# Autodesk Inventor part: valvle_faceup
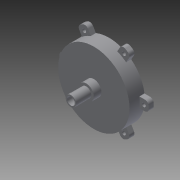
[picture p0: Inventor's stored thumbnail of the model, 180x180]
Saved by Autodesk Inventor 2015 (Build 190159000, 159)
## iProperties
Created: 2017-05
Part Number: valvle_faceup
Material: Generic
Document SubType Name: Modeling
Designer: mcalderon
Density: 1 g/cm^3
Appearance: Default
Author: mcalderon
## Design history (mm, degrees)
sketch "Sketch1"
  geometry: L1 (-25, 25)-(25, 25); L2 (25, 25)-(25, -25); L3 (25, -25)-(-25, -25); L4 (-25, -25)-(-25, 25); L5 (-25, 25)-(25, -25); L6 (25, 25)-(-25, -25); C1 r 25 at (0, 0); C2 r 28 at (0, 0); 1 further point
  constraints: 12 end point, 4 midpoint, 2 centre point, 2 parallel, 1 coincident, 1 horizontal, 1 perpendicular
  dimensions: "d0" = 50 diameter of C1; "d1" = 50 distance of L2.end L3.end; "d2" = 50 distance of L1.end L2.end; "d3" = 56 diameter of C2
extrude "Extrusion1" new body sketch "Sketch1" distance "d4" = 8; taper "d5" = 0 deg
sketch "Sketch2"
  geometry: L1 (-25, 0)-(-35, 0); L2 (-35, 0)-(-35, 1); L3 (-32, 4)-(-25, 4); L4 (-25, 4)-(-25, 0); L5 (-35, 0)-(-35, -1); L6 (-32, -4)-(-25, -4); L7 (-29.247, -4)-(-29.247, 4); L8 (-25, -4)-(-25, 0); L9 (-11.159, -27.329)-(-18.088, -23.329); L10 (-12.536, -29.713)-(-9.036, -23.651); L11 (-9.036, -23.651)-(-12.5, -21.651); L12 (-15.964, -19.651)-(-12.5, -21.651); L13 (-19.464, -25.713)-(-15.964, -19.651); L14 (-17.5, -30.311)-(-18.366, -29.811); L15 (-17.5, -30.311)-(-16.634, -30.811); L16 (18.088, -23.329)-(11.159, -27.329); L17 (19.464, -25.713)-(15.964, -19.651); L18 (15.964, -19.651)-(12.5, -21.651); L19 (9.036, -23.651)-(12.5, -21.651); L20 (12.536, -29.713)-(9.036, -23.651); L21 (17.5, -30.311)-(16.634, -30.811); L22 (17.5, -30.311)-(18.366, -29.811); L23 (29.247, 4)-(29.247, -4); L24 (32, 4)-(25, 4); L25 (25, 4)-(25, 0); L26 (25, -4)-(25, 0); L27 (32, -4)-(25, -4); L28 (35, 0)-(35, -1); L29 (35, 0)-(35, 1); L30 (11.159, 27.329)-(18.088, 23.329); L31 (12.536, 29.713)-(9.036, 23.651); L32 (9.036, 23.651)-(12.5, 21.651); L33 (15.964, 19.651)-(12.5, 21.651); L34 (19.464, 25.713)-(15.964, 19.651); L35 (17.5, 30.311)-(18.366, 29.811); L36 (17.5, 30.311)-(16.634, 30.811); L37 (-18.088, 23.329)-(-11.159, 27.329); L38 (-19.464, 25.713)-(-15.964, 19.651); L39 (-15.964, 19.651)-(-12.5, 21.651); L40 (-9.036, 23.651)-(-12.5, 21.651); L41 (-12.536, 29.713)-(-9.036, 23.651); L42 (-17.5, 30.311)-(-16.634, 30.811); L43 (-17.5, 30.311)-(-18.366, 29.811); C1 r 1.5 at (-31.163, 0); C2 r 1.5 at (-15.582, -26.988); C3 r 1.5 at (15.582, -26.988); C4 r 1.5 at (31.163, 0); C5 r 1.5 at (15.582, 26.988); C6 r 1.5 at (-15.582, 26.988); A1 r 3 centre (-32, -1) between (-35, -1) and (-32, -4); A2 r 3 centre (-32, 1) between (-32, 4) and (-35, 1); A3 r 3 centre (-16.866, -27.213) between (-19.464, -25.713) and (-18.366, -29.811); A4 r 3 centre (-15.134, -28.213) between (-16.634, -30.811) and (-12.536, -29.713); A5 r 3 centre (15.134, -28.213) between (12.536, -29.713) and (16.634, -30.811); A6 r 3 centre (16.866, -27.213) between (18.366, -29.811) and (19.464, -25.713); A7 r 3 centre (32, -1) between (32, -4) and (35, -1); A8 r 3 centre (32, 1) between (35, 1) and (32, 4); A9 r 3 centre (16.866, 27.213) between (19.464, 25.713) and (18.366, 29.811); A10 r 3 centre (15.134, 28.213) between (16.634, 30.811) and (12.536, 29.713); A11 r 3 centre (-15.134, 28.213) between (-12.536, 29.713) and (-16.634, 30.811); A12 r 3 centre (-16.866, 27.213) between (-18.366, 29.811) and (-19.464, 25.713); 14 further points
  constraints: 86 end point, 37 point on line, 24 point on circle, 18 centre point, 4 tangent, 3 vertical, 2 parallel, 2 symmetric about line, 1 equal radius, 1 horizontal, 1 horizontal alignment, 1 perpendicular, 152 other
  dimensions: "d6" = 10 distance of point (-35, 4) L3.end; "d7" = 4 distance of L1.end point (-35, 4); "d9" = 3 radius of A1; "d10" = 3 diameter of C1; "d13" = 360 deg dimension on point (0, 0) L7.start (derived)
extrude "Extrusion2" join sketch "Sketch2" distance "d15" = 4; taper "d16" = 0 deg
sketch "Sketch3"
  geometry: C1 r 28 at (0, 0); 1 further point
  constraints: 1 centre point, 1 coincident
  dimensions: "d17" = 56 diameter of C1
extrude "Extrusion3" join sketch "Sketch3" distance "d18" = 4; taper "d19" = 0 deg
sketch "Sketch4"
  geometry: C1 r 3.065 at (0, 0); 1 further point
  constraints: 1 centre point, 1 coincident
  dimensions: "d20" = 6.13 diameter of C1
extrude "Extrusion4" cut sketch "Sketch4" distance "d22" = 4; taper "d23" = 0 deg
sketch "Sketch5"
  geometry: C1 r 3.065 at (0, 0); C2 r 6 at (0, 0); 1 further point
  constraints: 2 centre point, 2 coincident
  dimensions: "d24" = 6.13 diameter of C1; "d25" = 12 diameter of C2
extrude "Extrusion5" join sketch "Sketch5" distance "d26" = 6; taper "d27" = 0 deg
sketch "Sketch6"
  geometry: C1 r 3.065 at (0, 0); C2 r 4 at (0, 0); 1 further point
  constraints: 2 centre point, 2 coincident
  dimensions: "d28" = 6.13 diameter of C1; "d29" = 8 diameter of C2
extrude "Extrusion6" join sketch "Sketch6" distance "d30" = 12; taper "d31" = 0 deg
sketch "Sketch7"
  geometry: C1 r 3.065 at (0, 0); C2 r 4.095 at (0, 0); 1 further point
  constraints: 2 centre point, 2 coincident
  dimensions: "d32" = 6.13 diameter of C1; "d33" = 8.19 diameter of C2
extrude "Extrusion7" join sketch "Sketch7" distance "d34" = 2.5; taper "d35" = 0 deg
body "Solid1"
